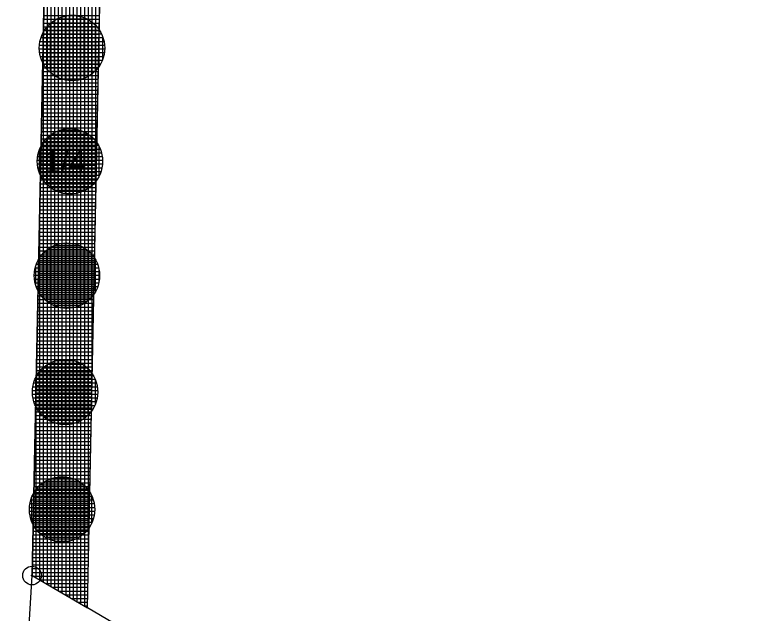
# Model space of a CAD drawing. Extents: x -566461 to -565198, y -1096301 to -1095707.
# Drawn here: x -565646 to -565606.25, y -1096010.79 to -1095978.77 of the extents above; entities that cross this region are included whole.
import ezdxf

# ---------------------------------------------------------------- set-up
doc = ezdxf.new("R2010")
doc.units = 0
for name, color, linetype in [('Vrstva 1', 7, 'Continuous'), ('Vrstva 24', 7, 'Continuous'), ('Vrstva 40', 7, 'Continuous'), ('Vrstva 43', 7, 'Continuous'), ('Vrstva 44', 7, 'Continuous')]:
    doc.layers.add(name, color=color, linetype=linetype)

msp = doc.modelspace()

# ---------------------------------------------------------------- linework, layer by layer
at = {"layer": 'Vrstva 1'}
for p, q in [((-565645.08, -1096008.78), (-565642.52, -1095885.6)), ((-565642.11, -1096010.51), (-565639.56, -1095885.89)), ((-565646, -1096024.36), (-565645.08, -1096008.78)), ((-565645.08, -1096008.78), (-565642.11, -1096010.51)), ((-565608.98, -1096029.79), (-565642.11, -1096010.51))]:
    msp.add_line(p, q, dxfattribs=at)
at = {"layer": 'Vrstva 24'}
for radius in [0.5, 0.0327]:
    msp.add_circle((-565645.08, -1096008.78), radius, dxfattribs=at)
at = {"layer": 'Vrstva 43'}
for p, q in [((-565642.06, -1096008.067), (-565642.06, -1095870.575)), ((-565641.86, -1095998.292), (-565641.86, -1095870.594)), ((-565641.66, -1095988.518), (-565641.66, -1095870.614)), ((-565642.26, -1096010.423), (-565642.26, -1095872.986)), ((-565642.46, -1096010.306), (-565642.46, -1095882.689)), ((-565642.66, -1096010.19), (-565642.66, -1095892.336)), ((-565642.86, -1096010.073), (-565642.86, -1095901.96)), ((-565643.06, -1096009.957), (-565643.06, -1095911.583)), ((-565643.26, -1096009.84), (-565643.26, -1095921.207)), ((-565643.46, -1096009.724), (-565643.46, -1095930.83)), ((-565643.66, -1096009.607), (-565643.66, -1095940.454)), ((-565643.86, -1096009.491), (-565643.86, -1095950.077)), ((-565644.06, -1096009.374), (-565644.06, -1095959.701)), ((-565644.26, -1096009.258), (-565644.26, -1095969.324)), ((-565644.461, -1095979.01), (-565641.465, -1095979.01)), ((-565644.46, -1096009.141), (-565644.46, -1095978.947)), ((-565644.457, -1095978.81), (-565641.461, -1095978.81)), ((-565644.47, -1095979.41), (-565641.474, -1095979.41)), ((-565644.465, -1095979.21), (-565641.47, -1095979.21)), ((-565644.478, -1095979.81), (-565641.482, -1095979.81)), ((-565644.474, -1095979.61), (-565641.478, -1095979.61)), ((-565644.486, -1095980.21), (-565641.49, -1095980.21)), ((-565644.482, -1095980.01), (-565641.486, -1095980.01)), ((-565644.495, -1095980.61), (-565641.498, -1095980.61)), ((-565644.49, -1095980.41), (-565641.494, -1095980.41)), ((-565644.503, -1095981.01), (-565641.506, -1095981.01)), ((-565644.499, -1095980.81), (-565641.502, -1095980.81)), ((-565644.511, -1095981.41), (-565641.515, -1095981.41)), ((-565644.507, -1095981.21), (-565641.51, -1095981.21)), ((-565644.519, -1095981.81), (-565641.523, -1095981.81)), ((-565644.515, -1095981.61), (-565641.519, -1095981.61)), ((-565644.528, -1095982.21), (-565641.531, -1095982.21)), ((-565644.524, -1095982.01), (-565641.527, -1095982.01)), ((-565644.536, -1095982.61), (-565641.539, -1095982.61)), ((-565644.532, -1095982.41), (-565641.535, -1095982.41)), ((-565644.544, -1095983.01), (-565641.547, -1095983.01)), ((-565644.54, -1095982.81), (-565641.543, -1095982.81)), ((-565644.553, -1095983.41), (-565641.555, -1095983.41)), ((-565644.549, -1095983.21), (-565641.551, -1095983.21)), ((-565644.561, -1095983.81), (-565641.564, -1095983.81)), ((-565644.557, -1095983.61), (-565641.56, -1095983.61)), ((-565644.569, -1095984.21), (-565641.572, -1095984.21)), ((-565644.565, -1095984.01), (-565641.568, -1095984.01)), ((-565644.578, -1095984.61), (-565641.58, -1095984.61)), ((-565644.574, -1095984.41), (-565641.576, -1095984.41)), ((-565644.586, -1095985.01), (-565641.588, -1095985.01)), ((-565644.582, -1095984.81), (-565641.584, -1095984.81)), ((-565644.594, -1095985.41), (-565641.596, -1095985.41)), ((-565644.59, -1095985.21), (-565641.592, -1095985.21)), ((-565644.603, -1095985.81), (-565641.605, -1095985.81)), ((-565644.598, -1095985.61), (-565641.6, -1095985.61)), ((-565644.611, -1095986.21), (-565641.613, -1095986.21)), ((-565644.607, -1095986.01), (-565641.609, -1095986.01)), ((-565644.619, -1095986.61), (-565641.621, -1095986.61)), ((-565644.615, -1095986.41), (-565641.617, -1095986.41)), ((-565644.628, -1095987.01), (-565641.629, -1095987.01)), ((-565644.623, -1095986.81), (-565641.625, -1095986.81)), ((-565644.636, -1095987.41), (-565641.637, -1095987.41)), ((-565644.632, -1095987.21), (-565641.633, -1095987.21)), ((-565644.644, -1095987.81), (-565641.646, -1095987.81)), ((-565644.64, -1095987.61), (-565641.641, -1095987.61)), ((-565644.653, -1095988.21), (-565641.654, -1095988.21)), ((-565644.648, -1095988.01), (-565641.65, -1095988.01)), ((-565644.661, -1095988.61), (-565641.662, -1095988.61)), ((-565644.66, -1096009.025), (-565644.66, -1095988.571)), ((-565644.657, -1095988.41), (-565641.658, -1095988.41)), ((-565644.669, -1095989.01), (-565641.67, -1095989.01)), ((-565644.665, -1095988.81), (-565641.666, -1095988.81)), ((-565644.677, -1095989.41), (-565641.678, -1095989.41)), ((-565644.673, -1095989.21), (-565641.674, -1095989.21)), ((-565644.686, -1095989.81), (-565641.686, -1095989.81)), ((-565644.682, -1095989.61), (-565641.682, -1095989.61)), ((-565644.694, -1095990.21), (-565641.695, -1095990.21)), ((-565644.69, -1095990.01), (-565641.691, -1095990.01)), ((-565644.698, -1095990.41), (-565641.699, -1095990.41)), ((-565644.707, -1095990.81), (-565641.707, -1095990.81)), ((-565644.702, -1095990.61), (-565641.703, -1095990.61)), ((-565644.715, -1095991.21), (-565641.715, -1095991.21)), ((-565644.711, -1095991.01), (-565641.711, -1095991.01)), ((-565644.723, -1095991.61), (-565641.723, -1095991.61)), ((-565644.719, -1095991.41), (-565641.719, -1095991.41)), ((-565644.731, -1095992.01), (-565641.731, -1095992.01)), ((-565644.727, -1095991.81), (-565641.727, -1095991.81)), ((-565644.74, -1095992.41), (-565641.74, -1095992.41)), ((-565644.736, -1095992.21), (-565641.736, -1095992.21)), ((-565644.748, -1095992.81), (-565641.748, -1095992.81)), ((-565644.744, -1095992.61), (-565641.744, -1095992.61)), ((-565644.756, -1095993.21), (-565641.756, -1095993.21)), ((-565644.752, -1095993.01), (-565641.752, -1095993.01)), ((-565644.765, -1095993.61), (-565641.764, -1095993.61)), ((-565644.761, -1095993.41), (-565641.76, -1095993.41)), ((-565644.773, -1095994.01), (-565641.772, -1095994.01)), ((-565644.769, -1095993.81), (-565641.768, -1095993.81)), ((-565644.781, -1095994.41), (-565641.781, -1095994.41)), ((-565644.777, -1095994.21), (-565641.776, -1095994.21)), ((-565644.79, -1095994.81), (-565641.789, -1095994.81)), ((-565644.786, -1095994.61), (-565641.785, -1095994.61)), ((-565644.798, -1095995.21), (-565641.797, -1095995.21)), ((-565644.794, -1095995.01), (-565641.793, -1095995.01)), ((-565644.806, -1095995.61), (-565641.805, -1095995.61)), ((-565644.802, -1095995.41), (-565641.801, -1095995.41)), ((-565644.815, -1095996.01), (-565641.813, -1095996.01)), ((-565644.81, -1095995.81), (-565641.809, -1095995.81)), ((-565644.823, -1095996.41), (-565641.821, -1095996.41)), ((-565644.819, -1095996.21), (-565641.817, -1095996.21)), ((-565644.831, -1095996.81), (-565641.83, -1095996.81)), ((-565644.827, -1095996.61), (-565641.826, -1095996.61)), ((-565644.84, -1095997.21), (-565641.838, -1095997.21)), ((-565644.835, -1095997.01), (-565641.834, -1095997.01)), ((-565644.848, -1095997.61), (-565641.846, -1095997.61)), ((-565644.844, -1095997.41), (-565641.842, -1095997.41)), ((-565644.856, -1095998.01), (-565641.854, -1095998.01)), ((-565644.852, -1095997.81), (-565641.85, -1095997.81)), ((-565644.864, -1095998.41), (-565641.862, -1095998.41)), ((-565644.86, -1096008.908), (-565644.86, -1095998.194)), ((-565644.86, -1095998.21), (-565641.858, -1095998.21)), ((-565644.873, -1095998.81), (-565641.871, -1095998.81)), ((-565644.869, -1095998.61), (-565641.866, -1095998.61)), ((-565644.881, -1095999.21), (-565641.879, -1095999.21)), ((-565644.877, -1095999.01), (-565641.875, -1095999.01)), ((-565644.889, -1095999.61), (-565641.887, -1095999.61)), ((-565644.885, -1095999.41), (-565641.883, -1095999.41)), ((-565644.898, -1096000.01), (-565641.895, -1096000.01)), ((-565644.894, -1095999.81), (-565641.891, -1095999.81)), ((-565644.906, -1096000.41), (-565641.903, -1096000.41)), ((-565644.902, -1096000.21), (-565641.899, -1096000.21)), ((-565644.914, -1096000.81), (-565641.912, -1096000.81)), ((-565644.91, -1096000.61), (-565641.907, -1096000.61)), ((-565644.923, -1096001.21), (-565641.92, -1096001.21)), ((-565644.919, -1096001.01), (-565641.916, -1096001.01)), ((-565644.931, -1096001.61), (-565641.928, -1096001.61)), ((-565644.927, -1096001.41), (-565641.924, -1096001.41)), ((-565644.939, -1096002.01), (-565641.936, -1096002.01)), ((-565644.935, -1096001.81), (-565641.932, -1096001.81)), ((-565644.948, -1096002.41), (-565641.944, -1096002.41)), ((-565644.943, -1096002.21), (-565641.94, -1096002.21)), ((-565644.956, -1096002.81), (-565641.952, -1096002.81)), ((-565644.952, -1096002.61), (-565641.948, -1096002.61)), ((-565644.964, -1096003.21), (-565641.961, -1096003.21)), ((-565644.96, -1096003.01), (-565641.957, -1096003.01)), ((-565644.973, -1096003.61), (-565641.969, -1096003.61)), ((-565644.968, -1096003.41), (-565641.965, -1096003.41)), ((-565644.981, -1096004.01), (-565641.977, -1096004.01)), ((-565644.977, -1096003.81), (-565641.973, -1096003.81)), ((-565644.989, -1096004.41), (-565641.985, -1096004.41)), ((-565644.985, -1096004.21), (-565641.981, -1096004.21)), ((-565644.997, -1096004.81), (-565641.993, -1096004.81)), ((-565644.993, -1096004.61), (-565641.989, -1096004.61)), ((-565645.006, -1096005.21), (-565642.002, -1096005.21)), ((-565645.002, -1096005.01), (-565641.997, -1096005.01)), ((-565645.014, -1096005.61), (-565642.01, -1096005.61)), ((-565645.01, -1096005.41), (-565642.006, -1096005.41)), ((-565645.022, -1096006.01), (-565642.018, -1096006.01)), ((-565645.018, -1096005.81), (-565642.014, -1096005.81)), ((-565645.031, -1096006.41), (-565642.026, -1096006.41)), ((-565645.027, -1096006.21), (-565642.022, -1096006.21)), ((-565645.039, -1096006.81), (-565642.034, -1096006.81)), ((-565645.035, -1096006.61), (-565642.03, -1096006.61)), ((-565645.047, -1096007.21), (-565642.042, -1096007.21)), ((-565645.043, -1096007.01), (-565642.038, -1096007.01)), ((-565645.056, -1096007.61), (-565642.051, -1096007.61)), ((-565645.052, -1096007.41), (-565642.047, -1096007.41)), ((-565645.064, -1096008.01), (-565642.059, -1096008.01)), ((-565645.06, -1096007.81), (-565642.055, -1096007.81)), ((-565645.06, -1096008.792), (-565645.06, -1096007.818)), ((-565645.072, -1096008.41), (-565642.067, -1096008.41)), ((-565645.068, -1096008.21), (-565642.063, -1096008.21)), ((-565645.076, -1096008.61), (-565642.071, -1096008.61)), ((-565645.028, -1096008.81), (-565642.075, -1096008.81)), ((-565644.685, -1096009.01), (-565642.079, -1096009.01)), ((-565644.342, -1096009.21), (-565642.083, -1096009.21)), ((-565643.998, -1096009.41), (-565642.087, -1096009.41)), ((-565643.655, -1096009.61), (-565642.092, -1096009.61)), ((-565643.312, -1096009.81), (-565642.096, -1096009.81)), ((-565642.968, -1096010.01), (-565642.1, -1096010.01)), ((-565642.625, -1096010.21), (-565642.104, -1096010.21)), ((-565642.282, -1096010.41), (-565642.108, -1096010.41))]:
    msp.add_line(p, q, dxfattribs=at)
msp.add_lwpolyline([(-565639.56, -1095885.89), (-565630.78, -1095886.75), (-565609.49, -1095886.27), (-565595.88, -1095884.74), (-565585.92, -1095883.62), (-565568.01, -1095880.69), (-565521.32, -1095878.21), (-565519.36, -1095863.08), (-565522.03, -1095863.23), (-565569.62, -1095865.76), (-565587.97, -1095868.76), (-565610.5, -1095871.29), (-565630.22, -1095871.73), (-565642.21, -1095870.56), (-565642.52, -1095885.6), (-565645.08, -1096008.78), (-565642.11, -1096010.51)], close=True, dxfattribs=at)
at = {"layer": 'Vrstva 44'}
for p, q in [((-565642.109, -1095979.01), (-565643.768, -1095979.01)), ((-565643.7, -1095978.975), (-565643.7, -1095982.125)), ((-565643.5, -1095978.894), (-565643.5, -1095982.206)), ((-565643.3, -1095978.839), (-565643.3, -1095982.262)), ((-565642.757, -1095978.81), (-565643.115, -1095978.81)), ((-565643.1, -1095978.808), (-565643.1, -1095982.291)), ((-565642.9, -1095978.801), (-565642.9, -1095982.298)), ((-565642.7, -1095978.818), (-565642.7, -1095982.282)), ((-565642.5, -1095978.858), (-565642.5, -1095982.243)), ((-565642.3, -1095978.923), (-565642.3, -1095982.177)), ((-565642.1, -1095979.016), (-565642.1, -1095982.083)), ((-565644.3, -1095979.452), (-565644.3, -1095981.649)), ((-565641.614, -1095979.41), (-565644.266, -1095979.41)), ((-565644.1, -1095979.242), (-565644.1, -1095981.858)), ((-565641.816, -1095979.21), (-565644.063, -1095979.21)), ((-565643.9, -1095979.088), (-565643.9, -1095982.013)), ((-565641.9, -1095979.145), (-565641.9, -1095981.957)), ((-565641.7, -1095979.316), (-565641.7, -1095981.782)), ((-565641.356, -1095979.81), (-565644.526, -1095979.81)), ((-565644.5, -1095979.761), (-565644.5, -1095981.339)), ((-565641.466, -1095979.61), (-565644.414, -1095979.61)), ((-565641.5, -1095979.556), (-565641.5, -1095981.541)), ((-565641.225, -1095980.21), (-565644.655, -1095980.21)), ((-565641.275, -1095980.01), (-565644.603, -1095980.01)), ((-565641.3, -1095979.945), (-565641.3, -1095981.161)), ((-565641.193, -1095980.61), (-565644.688, -1095980.61)), ((-565641.198, -1095980.41), (-565644.683, -1095980.41)), ((-565641.211, -1095980.81), (-565644.67, -1095980.81)), ((-565641.252, -1095981.01), (-565644.627, -1095981.01)), ((-565641.321, -1095981.21), (-565644.559, -1095981.21)), ((-565641.418, -1095981.41), (-565644.464, -1095981.41)), ((-565641.548, -1095981.61), (-565644.33, -1095981.61)), ((-565641.728, -1095981.81), (-565644.154, -1095981.81)), ((-565641.979, -1095982.01), (-565643.904, -1095982.01)), ((-565642.392, -1095982.21), (-565643.488, -1095982.21)), ((-565643.7, -1095984.986), (-565643.7, -1095988.235)), ((-565642.445, -1095984.97), (-565643.658, -1095984.97)), ((-565643.5, -1095984.92), (-565643.5, -1095988.3)), ((-565643.3, -1095984.88), (-565643.3, -1095988.341)), ((-565643.1, -1095984.863), (-565643.1, -1095988.359)), ((-565642.9, -1095984.868), (-565642.9, -1095988.352)), ((-565642.7, -1095984.896), (-565642.7, -1095988.323)), ((-565642.5, -1095984.95), (-565642.5, -1095988.269)), ((-565642.3, -1095985.031), (-565642.3, -1095988.191)), ((-565644.3, -1095985.388), (-565644.3, -1095987.832)), ((-565641.816, -1095985.37), (-565644.282, -1095985.37)), ((-565644.1, -1095985.211), (-565644.1, -1095988.008)), ((-565642.057, -1095985.17), (-565644.041, -1095985.17)), ((-565643.9, -1095985.083), (-565643.9, -1095988.138)), ((-565642.1, -1095985.141), (-565642.1, -1095988.078)), ((-565641.9, -1095985.293), (-565641.9, -1095987.927)), ((-565641.515, -1095985.77), (-565644.583, -1095985.77)), ((-565644.5, -1095985.634), (-565644.5, -1095987.587)), ((-565641.645, -1095985.57), (-565644.457, -1095985.57)), ((-565641.7, -1095985.497), (-565641.7, -1095987.72)), ((-565641.5, -1095985.801), (-565641.5, -1095987.419)), ((-565641.358, -1095986.17), (-565644.743, -1095986.17)), ((-565644.7, -1095986.027), (-565644.7, -1095987.191)), ((-565641.423, -1095985.97), (-565644.677, -1095985.97)), ((-565641.301, -1095986.57), (-565644.798, -1095986.57)), ((-565641.318, -1095986.37), (-565644.783, -1095986.37)), ((-565641.309, -1095986.77), (-565644.791, -1095986.77)), ((-565641.339, -1095986.97), (-565644.761, -1095986.97)), ((-565641.394, -1095987.17), (-565644.708, -1095987.17)), ((-565641.474, -1095987.37), (-565644.625, -1095987.37)), ((-565641.589, -1095987.57), (-565644.511, -1095987.57)), ((-565641.741, -1095987.77), (-565644.359, -1095987.77)), ((-565641.952, -1095987.97), (-565644.15, -1095987.97)), ((-565642.26, -1095988.17), (-565643.842, -1095988.17)), ((-565643.5, -1095991.005), (-565643.5, -1095994.454)), ((-565643.3, -1095990.984), (-565643.3, -1095994.476)), ((-565643.1, -1095990.985), (-565643.1, -1095994.476)), ((-565644.3, -1095991.362), (-565644.3, -1095994.099)), ((-565642.163, -1095991.33), (-565644.258, -1095991.33)), ((-565644.1, -1095991.225), (-565644.1, -1095994.235)), ((-565642.504, -1095991.13), (-565643.914, -1095991.13)), ((-565643.9, -1095991.124), (-565643.9, -1095994.337)), ((-565643.7, -1095991.051), (-565643.7, -1095994.41)), ((-565642.9, -1095991.009), (-565642.9, -1095994.451)), ((-565642.7, -1095991.056), (-565642.7, -1095994.402)), ((-565642.5, -1095991.132), (-565642.5, -1095994.328)), ((-565642.3, -1095991.237), (-565642.3, -1095994.225)), ((-565642.1, -1095991.377), (-565642.1, -1095994.08)), ((-565641.775, -1095991.73), (-565644.645, -1095991.73)), ((-565644.5, -1095991.549), (-565644.5, -1095993.91)), ((-565641.939, -1095991.53), (-565644.481, -1095991.53)), ((-565641.9, -1095991.572), (-565641.9, -1095993.889)), ((-565641.568, -1095992.13), (-565644.853, -1095992.13)), ((-565641.655, -1095991.93), (-565644.764, -1095991.93)), ((-565644.7, -1095991.815), (-565644.7, -1095993.644)), ((-565641.7, -1095991.848), (-565641.7, -1095993.612)), ((-565641.472, -1095992.53), (-565644.947, -1095992.53)), ((-565641.507, -1095992.33), (-565644.913, -1095992.33)), ((-565644.9, -1095992.28), (-565644.9, -1095993.178)), ((-565641.5, -1095992.36), (-565641.5, -1095993.093)), ((-565641.462, -1095992.73), (-565644.958, -1095992.73)), ((-565641.473, -1095992.93), (-565644.947, -1095992.93)), ((-565641.508, -1095993.13), (-565644.914, -1095993.13)), ((-565641.567, -1095993.33), (-565644.852, -1095993.33)), ((-565641.655, -1095993.53), (-565644.764, -1095993.53)), ((-565641.776, -1095993.73), (-565644.646, -1095993.73)), ((-565641.938, -1095993.93), (-565644.481, -1095993.93)), ((-565642.16, -1095994.13), (-565644.257, -1095994.13)), ((-565642.506, -1095994.33), (-565643.914, -1095994.33)), ((-565643.9, -1095997.314), (-565643.9, -1096000.606)), ((-565642.788, -1095997.29), (-565643.828, -1095997.29)), ((-565643.7, -1095997.256), (-565643.7, -1096000.666)), ((-565643.5, -1095997.222), (-565643.5, -1096000.699)), ((-565643.3, -1095997.211), (-565643.3, -1096000.708)), ((-565643.1, -1095997.223), (-565643.1, -1096000.695)), ((-565642.9, -1095997.261), (-565642.9, -1096000.66)), ((-565642.7, -1095997.322), (-565642.7, -1096000.6)), ((-565642.108, -1095997.69), (-565644.513, -1095997.69)), ((-565644.5, -1095997.677), (-565644.5, -1096000.242)), ((-565644.3, -1095997.519), (-565644.3, -1096000.401)), ((-565642.362, -1095997.49), (-565644.258, -1095997.49)), ((-565644.1, -1095997.399), (-565644.1, -1096000.521)), ((-565642.5, -1095997.41), (-565642.5, -1096000.509)), ((-565642.3, -1095997.533), (-565642.3, -1096000.387)), ((-565642.1, -1095997.697), (-565642.1, -1096000.222)), ((-565641.793, -1095998.09), (-565644.827, -1095998.09)), ((-565644.7, -1095997.899), (-565644.7, -1096000.02)), ((-565641.928, -1095997.89), (-565644.693, -1095997.89)), ((-565641.9, -1095997.926), (-565641.9, -1095999.995)), ((-565641.626, -1095998.49), (-565644.994, -1095998.49)), ((-565641.695, -1095998.29), (-565644.925, -1095998.29)), ((-565644.9, -1095998.23), (-565644.9, -1095999.69)), ((-565641.7, -1095998.276), (-565641.7, -1095999.641)), ((-565641.562, -1095998.89), (-565645.058, -1095998.89)), ((-565641.583, -1095998.69), (-565645.039, -1095998.69)), ((-565641.565, -1095999.09), (-565645.053, -1095999.09)), ((-565641.593, -1095999.29), (-565645.027, -1095999.29)), ((-565641.644, -1095999.49), (-565644.976, -1095999.49)), ((-565641.721, -1095999.69), (-565644.9, -1095999.69)), ((-565641.829, -1095999.89), (-565644.79, -1095999.89)), ((-565641.976, -1096000.09), (-565644.645, -1096000.09)), ((-565642.175, -1096000.29), (-565644.444, -1096000.29)), ((-565642.465, -1096000.49), (-565644.156, -1096000.49)), ((-565643.054, -1096000.69), (-565643.564, -1096000.69)), ((-565644.3, -1096003.701), (-565644.3, -1096006.779)), ((-565644.1, -1096003.607), (-565644.1, -1096006.872)), ((-565643.023, -1096003.55), (-565643.921, -1096003.55)), ((-565643.9, -1096003.545), (-565643.9, -1096006.935)), ((-565643.7, -1096003.507), (-565643.7, -1096006.974)), ((-565643.5, -1096003.492), (-565643.5, -1096006.989)), ((-565643.3, -1096003.499), (-565643.3, -1096006.98)), ((-565643.1, -1096003.53), (-565643.1, -1096006.948)), ((-565642.9, -1096003.587), (-565642.9, -1096006.893)), ((-565642.7, -1096003.671), (-565642.7, -1096006.811)), ((-565644.7, -1096003.998), (-565644.7, -1096006.483)), ((-565642.29, -1096003.95), (-565644.651, -1096003.95)), ((-565644.5, -1096003.827), (-565644.5, -1096006.652)), ((-565642.556, -1096003.75), (-565644.387, -1096003.75)), ((-565642.5, -1096003.783), (-565642.5, -1096006.694)), ((-565642.3, -1096003.941), (-565642.3, -1096006.541)), ((-565641.965, -1096004.35), (-565644.977, -1096004.35)), ((-565644.9, -1096004.233), (-565644.9, -1096006.249)), ((-565642.103, -1096004.15), (-565644.837, -1096004.15)), ((-565642.1, -1096004.154), (-565642.1, -1096006.326)), ((-565641.9, -1096004.471), (-565641.9, -1096006.012)), ((-565641.792, -1096004.75), (-565645.148, -1096004.75)), ((-565645.1, -1096004.608), (-565645.1, -1096005.871)), ((-565641.862, -1096004.55), (-565645.076, -1096004.55)), ((-565641.724, -1096005.15), (-565645.217, -1096005.15)), ((-565641.746, -1096004.95), (-565645.195, -1096004.95)), ((-565641.724, -1096005.35), (-565645.215, -1096005.35)), ((-565641.749, -1096005.55), (-565645.19, -1096005.55)), ((-565641.798, -1096005.75), (-565645.142, -1096005.75)), ((-565641.872, -1096005.95), (-565645.069, -1096005.95)), ((-565641.975, -1096006.15), (-565644.963, -1096006.15)), ((-565642.12, -1096006.35), (-565644.821, -1096006.35)), ((-565642.311, -1096006.55), (-565644.627, -1096006.55)), ((-565642.588, -1096006.75), (-565644.351, -1096006.75)), ((-565643.107, -1096006.95), (-565643.84, -1096006.95))]:
    msp.add_line(p, q, dxfattribs=at)
for centre in [(-565642.94, -1095980.55), (-565643.05, -1095986.61), (-565643.21, -1095992.73), (-565643.31, -1095998.96), (-565643.47, -1096005.24)]:
    msp.add_circle(centre, 1.75, dxfattribs=at)

# ---------------------------------------------------------------- texts
at = {"layer": 'Vrstva 40'}
msp.add_text('1/4', height=1.2, dxfattribs=at).set_placement((-565644.44, -1095987.22))

doc.saveas('drawing.dxf')
